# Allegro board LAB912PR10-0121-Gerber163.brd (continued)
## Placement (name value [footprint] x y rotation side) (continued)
PR501  499_0402_1%  [R_0402]  118.02 153.56 270 bottom
PR502  2K_0402_1%  [R_0402]  116.16 147.96 0 top
PR503  137K_0402_1%  [R_0402]  118.92 148.85 180 bottom
PR504  2.05K_0402_1%  [R_0402]  118.9 151.51 180 bottom
PR505  2K_0402_1%  [R_0402]  117.11 150.56 270 bottom
PR506  0_0603_5%  [R0603_0OHM]  118.29 139.4 270 top
PR507  215_0402_1%  [R_0402]  117.13 147.02 270 top
PR508  21K_0402_1%  [R_0402]  118.92 147.96 180 bottom
PR509  11K_0402_1%  [R_0402]  118.01 150.06 0 top
PR510  1.91K_0402_1%  [R_0402]  117.05 146.95 0 bottom
PR511  0_0603_5%  [R0603_0OHM]  118.1 145.84 270 bottom
PR512  4.7_0603_5%  [R_0603]  121.66 134.2 0 top
PR513  3.65K_0603_1%  [R_0603]  114.52 151.52 0 top
PR514  61.9K_0402_1%  [R_0402]  123.29 149.65 90 top
PR515  3.83K_0402_1%  [R_0402]  120.17 153.34 270 bottom
PR516  0_0402_5%  [R0402_0OHM]  121.19 153.37 270 bottom
PR518  0_0603_5%  [R0603_0OHM]  121.82 143.58 270 bottom
PR519  1_0603_5%  [R_0603]  124.79 142.11 90 bottom
PR520  20_0402_1%  [R_0402]  122.37 153.3 270 bottom
PR521  16.9_0402_1%  [R_0402]  123.26 153.3 270 bottom
PR522  1.91K_0402_1%  [R_0402]  123.22 143.34 270 bottom
PR523  3.83K_0402_1%  [R_0402]  125.04 152.37 90 bottom
PR524  0_0402_5%  [R0402_0OHM]  126.82 153.29 270 bottom
PR525  499_0402_1%  [R_0402]  125.04 152.41 180 top
PR526  69.8_0402_1%  [R_0402]  123.26 153.3 270 top
PR527  69.8_0402_1%  [R_0402]  122.37 153.3 270 top
PR528  0_0603_5%  [R0603_0OHM]  134.49 135.72 180 top
PR529  61.9K_0402_1%  [R_0402]  125.93 153.29 270 bottom
PR530  1.91K_0402_1%  [R_0402]  127.7 147.07 0 bottom
PR531  0_0603_5%  [R0603_0OHM]  128.34 146.09 270 bottom
PR532  4.7_0603_5%  [R_0603]  129.41 134.2 180 top
PR533  2K_0402_1%  [R_0402]  129.49 149.72 90 bottom
PR534  64.9K_0402_1%  [R_0402]  128.61 147.96 180 bottom
PR535  2.61K_0402_1%  [R_0402]  128.48 151.01 0 top
PR536  3.65K_0603_1%  [R_0603]  129.63 152.15 180 top
PR538  499_0402_1%  [R_0402]  127.79 152.48 270 bottom
PR539  2K_0402_1%  [R_0402]  128.99 146.06 0 top
PR540  182_0402_1%  [R_0402]  128.99 146.95 0 top
PR541  11K_0402_1%  [R_0402]  128.48 150.12 0 top
PR542  1.78K_0402_1%  [R_0402]  128.81 152.48 270 bottom
PR543  137K_0402_1%  [R_0402]  128.6 150.64 270 bottom
PR700  0.01_1206_1%  [R_1206_4P-D]  118.8 164.04 0 bottom
PR701  200K_0402_1%  [R_0402]  95.59 150.74 270 top
PR702  200K_0402_1%  [R_0402]  136.84 163.71 90 top
PR703  150K_0402_1%  [R_0402]  132.01 170.72 270 top
PR704  10_0402_5%  [R_0402]  137.93 157.02 90 top
PR705  10_0402_5%  [R_0402]  137.04 157.02 90 top
PR706  200K_0402_1%  [R_0402]  158.68 164.73 90 top
PR707  10_1206_1%  [R_1206]  147.5 159.66 270 top
PR708  47K_0402_1%  [R_0402]  159.7 165.64 270 top
PR709  4.7_0603_5%  [R_0603]  147.55 156.55 90 bottom
PR710  100K_0402_1%  [R_0402]  144.89 148.66 90 top
PR711  232K_0402_1%  [R_0402]  137.85 154.6 180 top
PR712  200K_0402_5%  [R_0402]  133.03 170.72 270 top
PR713  0_0603_5%  [R0603_0OHM]  143.49 159.85 270 bottom
PR714  100K_0402_1%  [R_0402]  158.63 169.76 180 top
PR715  49.9K_0402_1%  [R_0402]  140.9 153.49 180 bottom
PR716  158K_0402_1%  [R_0402]  143.87 149.58 270 top
PR717  0_0402_5%  [R0402_0OHM]  142.35 148.66 90 top
PR718  10K_0402_5%  [R_0402]  137.34 170.72 270 top
PR719  0_0402_5%  [R0402_0OHM]  141.46 148.66 90 top
PR720  0.01_1206_1%  [R_1206_4P-D]  164.27 154.43 90 bottom
PR721  4.7_1206_5%  [R_1206]  156.97 152.48 180 top
PR722  100_0402_1%  [R_0402]  140.52 148.66 90 top
PR723  4.7K_0402_5%  [R_0402]  138.23 150.52 180 top
PR724  10_0402_5%  [R_0402]  148.95 151.96 90 top
PR725  221K_0402_1%  [R_0402]  137.32 152.42 0 top
PR726  100_0402_5%  [R_0402]  146.67 151.23 270 top
PR727  287K_0402_1%  [R_0402]  137.32 153.44 0 top
PR728  28.7K_0402_1%  [R_0402]  137.32 151.4 0 top
PR729  63.4K_0402_1%  [R_0402]  136.38 152.47 90 top
PR730  3.3K_1206_5%~D  [R_1206]  137.92 161.37 180 top
PU100  TPS51225CRUKR QFN 20P PWM  [TPS51225CRUKR_QFN20_3X3]  39.1 48.61 180 top
PU200  -  [RT8207MZQW_WQFN20_3X3]  58.93 51.3 180 top
PU300  -  [SY8032ABC_SOT23-6]  161.66 99.08 270 bottom
PU301  -  [SY8032ABC_SOT23-6]  155.05 117.62 270 bottom
PU400  -  [SY8032ABC_SOT23-6]  45.83 21.23 90 top
PU402  -  [APL5930KAI-TRG_SO8]  157.98 86.6 180 bottom
PU500  -  [ISL95833HRTZ-T_TQFN32_4X4]  121.9 150.5 0 bottom
PU700  ISL88731CHRTZ-T TQFN 28P PWM  [BQ24745RHDR_QFN28_5X5]  140.33 155.27 270 top
Q8  -  [2N7002K_SOT23-3]  166.24 67.31 0 top
Q9  -  [2N7002K_SOT23-3]  108.54 163.14 180 top
Q14  -  [DMN66D0LDW-7_SOT363-6]  20.87 68.22 0 top
Q57  -  [MESS138W-G_SOT323-3]  15.65 71.08 270 bottom
Q58  -  [MESS138W-G_SOT323-3]  15.65 68.54 270 bottom
Q70  -  [2N7002K_SOT23-3]  152.1 92.79 270 bottom
Q71  -  [2N7002K_SOT23-3]  158.65 106.89 90 bottom
Q2307  -  [2N7002K_SOT23-3]  130.36 39.07 90 top
Q2308  -  [2N7002K_SOT23-3]  161.09 81.47 180 bottom
Q2407  -  [MMST3904-7-F_SOT323-3]  58.39 65.53 270 bottom
Q2408  -  [MMST3904-7-F_SOT323-3]  138.02 130.79 180 top
Q6101  DDTA144VCA-7-F-GP  [2N7002K_SOT23-3]  29.46 8.3 0 top
Q6102  DDTA144VCA-7-F-GP  [2N7002K_SOT23-3]  29.48 13 0 top
Q6103  -  [2N7002KW_SOT323-3]  33.83 13.61 0 top
Q6104  DDTA144VCA-7-F-GP  [2N7002K_SOT23-3]  29.43 3.56 0 top
Q6105  -  [2N7002KW_SOT323-3]  145.4 146.68 90 bottom
QA1  DMN66D0LDW-7_SOT363-6~D  [DMN66D0LDW-7_SOT363-6]  160.52 23.69 90 bottom
QA5  -  [DMN66D0LDW-7_SOT363-6]  144.64 26.39 270 bottom
QC1  -  [MESS138W-G_SOT323-3]  138.36 110.13 180 top
QC2  -  [MESS138W-G_SOT323-3]  117.36 114.62 0 top
QC3  -  [MESS138W-G_SOT323-3]  129.04 112.08 0 top
QC4  -  [MESS138W-G_SOT323-3]  131.58 112.08 0 top
QE7  -  [MESS138W-G_SOT323-3]  58.03 72.73 90 bottom
QE8  -  [MESS138W-G_SOT323-3]  58.03 75.27 90 bottom
QE9  -  [MESS138W-G_SOT323-3]  58.03 75.27 270 top
QE10  -  [MESS138W-G_SOT323-3]  101.72 145.81 180 bottom
QE11  -  [MESS138W-G_SOT323-3]  104.07 145.81 180 bottom
QE12  -  [MESS138W-G_SOT323-3]  111.77 160.28 180 top
QM30  -  [2N7002K_SOT23-3]  158.93 49.64 0 bottom
QS2  SI3456BDV-T1-E3 1N TSOP6  [SI3456BDV-T1-E3_TSOP6]  169.97 81.68 180 bottom
QS3  -  [2N7002KW_SOT323-3]  167.48 75.52 270 bottom
R1  47K_0402_5%  [R_0402]  16.14 80.09 180 top
R3  4.7K_0402_5%  [R_0402]  90.4 78.57 0 top
R4  4.7K_0402_5%  [R_0402]  82.78 64.09 0 top
R7  4.7K_0402_5%  [R_0402]  82.78 76.28 0 top
R8  4.7K_0402_5%  [R_0402]  119.18 114.43 90 top
R9  4.7K_0402_5%  [R_0402]  91.32 81.11 180 top
R10  100K_0402_5%  [R_0402]  163.7 67.38 90 top
R11  4.7K_0402_5%  [R_0402]  83.79 70.73 180 top
R16  100K_0402_5%  [R_0402]  168.84 69.38 270 top
R22  0_0402_1%  [R0402_0OHM]  96.2 76.84 90 top
R23  0_0402_1%  [R0402_0OHM]  113.52 117.94 0 top
R24  0_0402_1%  [R0402_0OHM]  97.42 75.01 180 top
R25  0_0402_1%  [R0402_0OHM]  93.1 83.52 180 top
R26  0_0402_1%  [R0402_0OHM]  85.2 65.11 0 top
R27  0_0402_1%  [R0402_0OHM]  84.82 81.24 0 top
R28  0_0402_1%  [R0402_0OHM]  88.7 67.22 270 top
R29  0_0402_1%  [R0402_0OHM]  120.63 116.29 0 top
R30  0_0402_5%  [R_0402]  88.12 69.93 0 top
R31  0_0402_1%  [R0402_0OHM]  84.49 77.43 0 top
R32  0_0402_1%  [R0402_0OHM]  91.32 80.2 180 top
R34  0_0402_1%  [R0402_0OHM]  83.79 69.82 180 top
R36  0_0402_1%  [R0402_0OHM]  54.84 76.25 270 top
R44  0_0402_1%  [R0402_0OHM]  153.98 133.18 90 top
R121  100K_0402_5%  [R_0402]  19.74 68.21 90 top
R122  100K_0402_5%  [R_0402]  21.77 71.25 90 top
R376  10K_0402_5%  [R_0402]  20.76 72.17 270 top
R488  10K_0402_5%  [R_0402]  157.66 150.15 270 bottom
R490  10K_0402_5%  [R_0402]  163.84 51.77 180 top
R696  10K_0402_5%  [R_0402]  147.2 136.99 180 bottom
R697  10K_0402_5%  [R_0402]  147.2 133.69 180 bottom
R926  120K_0402_5%  [R_0402]  65.16 24.85 180 top
R927  100K_0402_5%  [R_0402]  64.24 20.4 0 top
R1022  0_0603_5%  [R0603_0OHM]  109.91 99.59 270 top
R1023  0_0603_5%  [R0603_0OHM]  134.3 99.84 270 top
R1024  10K_0402_5%  [R_0402]  96.5 74 0 top
R1027  4.7K_0402_1%  [R_0402]  69.97 35.49 90 top
R1028  4.7K_0402_1%  [R_0402]  70.99 35.49 90 top
R1029  4.7K_0402_1%  [R_0402]  114.48 29.09 90 top
R1030  4.7K_0402_1%  [R_0402]  113.47 29.09 90 top
R1033  10K_0402_5%  [R_0402]  92.18 84.41 0 top
R1045  0_0603_5%  [R_0603]  147.95 55.71 180 bottom
R1046  10K_0402_5%  [R_0402]  150.04 50.17 90 top
R1047  100K_0402_5%  [R_0402]  143.44 53.88 270 bottom
R1048  2.7K_0402_1%  [R_0402]  144.2 42.96 270 bottom
R1049  0_0402_1%  [R0402_0OHM]  153.04 43.01 180 bottom
R1050  0_0603_5%  [R0603_0OHM]  150.49 52.92 180 bottom
R1051  10K_0402_5%  [R_0402]  151.06 53.37 270 top
R1052  470_0603_5%  [R_0603]  159.25 104.22 180 bottom
R1053  0_0603_5%  [R_0603]  159.43 38.79 180 bottom
R1055  82K_0402_5%  [R_0402]  157.54 79.59 0 bottom
R1056  47K_0402_5%  [R_0402]  157.54 77.3 0 bottom
R1061  10K_0402_5%  [R_0402]  149.33 96.48 0 bottom
R1071  619_0402_1%  [R_0402]  21.22 64.73 0 top
R1072  619_0402_1%  [R_0402]  21.22 63.71 0 top
R1073  619_0402_1%  [R_0402]  21.22 66.76 0 top
R1074  619_0402_1%  [R_0402]  21.22 65.74 0 top
R1075  619_0402_1%  [R_0402]  21.22 62.69 0 top
R1076  619_0402_1%  [R_0402]  21.22 61.68 0 top
R1077  619_0402_1%  [R_0402]  21.22 60.66 0 top
R1078  619_0402_1%  [R_0402]  21.22 59.65 0 top
R1088  0_0402_5%  [R_0402]  96 83.45 45 bottom
R1089  0_0402_5%  [R_0402]  96.63 82.82 45 bottom
R2314  22_0603_5%  [R_0603]  132.58 37.42 180 top
R2315  470_0603_5%  [R_0603]  160.01 79.33 0 bottom
R2354  0_0402_5%  [R_0402]  155.42 150.16 270 bottom
R2355  0_0402_5%  [R_0402]  145.93 19.64 180 bottom
R2356  0_0402_5%  [R_0402]  153.85 25.53 90 bottom
R2358  8.2_0402_1%  [R_0402]  18.17 64.73 180 bottom
R2359  8.2_0402_1%  [R_0402]  18.17 63.71 180 bottom
R2360  8.2_0402_1%  [R_0402]  18.17 66.76 180 bottom
R2361  8.2_0402_1%  [R_0402]  18.17 65.74 180 bottom
R2362  8.2_0402_1%  [R_0402]  18.17 62.7 180 bottom
R2363  8.2_0402_1%  [R_0402]  18.17 61.68 180 bottom
R2364  8.2_0402_1%  [R_0402]  18.17 59.65 180 bottom
R2365  8.2_0402_1%  [R_0402]  18.17 60.66 180 bottom
R2366  0_0402_1%  [R0402_0OHM]  22.46 38.31 0 bottom
R2367  0_0402_1%  [R0402_0OHM]  22.46 37.3 0 bottom
R2368  0_0402_1%  [R0402_0OHM]  22.46 40.34 0 bottom
R2369  0_0402_1%  [R0402_0OHM]  22.46 39.33 0 bottom
R2448  10K_0402_5%  [R_0402]  107.45 109.81 180 top
R2449  2.2K_0402_5%  [R_0402]  107.45 111.84 180 top
R2450  0_0402_5%  [R_0402]  106.53 108.8 0 top
R2451  2.2K_0402_5%  [R_0402]  107.45 110.83 180 top
R3405  100K_0402_5%  [R_0402]  108.78 159.29 0 top
R3406  10K_0402_5%  [R_0402]  112.2 164.21 180 top
R5205  33_0402_5%  [R_0402]  113.96 161.2 90 top
R6103  470R2J-2-GP  [R_0402]  21.09 3.59 0 top
R6104  0_0402_1%  [R0402_0OHM]  31.95 14.92 270 top
R6105  0_0402_1%  [R0402_0OHM]  31.91 10.38 90 top
R6106  0R2J-2-GP  [R_0402]  31.91 5.04 90 top
R6107  390R2J-3-GP  [R_0402]  19.34 3.59 0 top
R6108  330R2J-3-GP  [R_0402]  23.78 3.6 180 top
R6110  10KR2J-3-GP  [R_0402]  148.27 149.89 270 bottom
RA1  100K_0402_5%  [R_0402]  143.69 23.66 270 bottom
RA2  100K_0402_5%  [R_0402]  141.53 25.15 90 bottom
RA3  10K_0402_5%  [R_0402]  144.71 22.74 90 bottom
RA4  0_0402_5%  [R_0402]  145.73 23.66 270 bottom
RA8  0_0402_1%  [R0402_0OHM]  152.63 8.97 0 bottom
RA16  100K_0402_5%~D  [R_0402]  161.6 27.08 270 bottom
RA17  100K_0402_5%~D  [R_0402]  162.49 27.08 270 bottom
RA18  10K_0402_5%~D  [R_0402]  160.71 26.17 90 bottom
RA19  10K_0402_5%  [R_0402]  142.47 19.64 0 bottom
RA20  100K_0402_5%~D  [R_0402]  159.62 22.69 0 bottom
RA29  0_0603_5%  [R_0603]  155.89 8.15 270 bottom
RA30  0_0603_5%  [R_0603]  159.31 25.8 90 bottom
RA31  0_0603_5%  [R_0603]  166.05 21.1 270 bottom
RA32  0_0603_5%  [R_0603]  160.2 8.15 270 bottom
RA34  200K_0402_1%  [R_0402]  148.34 23.71 180 bottom
RA53  2.2K_0402_5%  [R_0402]  150.3 22.99 90 bottom
RA54  10K_0402_5%  [R_0402]  155.63 128.05 270 bottom
RA55  10_0402_1%  [R_0402]  157.21 17.48 0 bottom
RA56  10_0402_1%  [R_0402]  157.21 16.59 0 bottom
RA79  1K_0402_1%  [R_0402]  143.39 20.66 180 bottom
RA80  1K_0402_1%  [R_0402]  157.21 18.37 0 top
RA81  10K_0402_5%  [R_0402]  142.47 21.67 0 bottom
RA82  1K_0402_1%  [R_0402]  157.21 19.26 0 top
RA83  10K_0402_5%  [R_0402]  158.12 17.48 180 top
RA84  10K_0402_5%  [R_0402]  158.12 16.59 180 top
RA130  22_0402_5%  [R_0402]  132.83 106.8 45 bottom
RA154  100K_0402_5%  [R_0402]  160.53 21.67 180 bottom
RA155  100K_0402_5%  [R_0402]  148.34 22.82 180 bottom
RA165  4.7K_0402_5%  [R_0402]  157.21 18.37 0 bottom
RA166  4.7K_0402_5%  [R_0402]  157.21 19.26 0 bottom
RA1109  2.2K_0402_5%  [R_0402]  149.28 22.99 90 bottom
RC1  100K_0402_5%  [R_0402]  131.87 85.76 135 top
RC2  100K_0402_5%  [R_0402]  132.5 86.4 135 top
RC3  23.2_0402_1%  [R_0402]  130.6 84.49 135 top
RC4  29.4_0402_1%  [R_0402]  131.23 85.13 135 top
RC5  162_0402_1%  [R_0402]  129.96 83.86 135 top
RC6  4.7K_0402_1%  [R_0402]  136.57 80.99 90 bottom
RC7  4.7K_0402_1%  [R_0402]  135.68 80.99 90 bottom
RC8  2.2K_0402_5%  [R_0402]  119.13 84.69 225 top
RC9  402_0402_1%  [R_0402]  119.59 99.01 225 top
RC10  10K_0402_5%  [R_0402]  110.95 77.41 135 bottom
RC11  10K_0402_5%  [R_0402]  111.07 78.81 315 bottom
RC12  402_0402_1%  [R_0402]  122.93 98.93 45 top
RC13  402_0402_1%  [R_0402]  120.86 99 135 top
RC14  49.9_0402_1%  [R_0402]  131.01 104.51 45 bottom
RC15  73.2_0402_1%  [R_0402]  107.81 82.56 45 bottom
RC16  10K_0402_5%  [R_0402]  129.75 96.24 135 top
RC17  10K_0402_5%  [R_0402]  140.34 109.81 180 top
RC18  10K_0402_5%  [R_0402]  116.52 111.64 0 top
RC19  1M_0402_5%  [R_0402]  111.71 103.71 225 bottom
RC20  4.7K_0402_5%  [R_0402]  90.4 69.55 0 top
RC21  2.2K_0402_5%  [R_0402]  110.62 85.5 225 top
RC22  47.5_0402_1%  [R_0402]  113.74 97.44 315 top
RC23  4.02K_0402_1%  [R_0402]  114.94 96.18 315 top
RC24  0_0402_5%  [R_0402]  124.92 110.68 135 bottom
RC26  100K_0402_5%  [R_0402]  97.41 86.39 225 bottom
RC27  73.2_0402_1%  [R_0402]  105.53 77.6 45 bottom
RC28  20_0402_1%  [R_0402]  107.45 79.51 225 bottom
RC29  16.9_0402_1%  [R_0402]  109.56 81.35 225 bottom
RC30  10K_0402_5%  [R_0402]  83.5 72.52 90 top
RC31  10M_0402_5%  [R_0402]  101.49 90.6 315 bottom
RC32  49.9_0402_1%  [R_0402]  116.14 89.03 0 top
RC33  1K_0402_5%  [R_0402]  54.59 8.47 0 bottom
RC34  20K_0402_1%  [R_0402]  95.36 84.09 45 bottom
RC35  20K_0402_1%  [R_0402]  103.24 87.02 315 bottom
RC36  3.3K_0402_5%  [R_0402]  91.67 68.37 0 bottom
RC37  3.3K_0402_5%  [R_0402]  103.99 70.23 180 bottom
RC38  3.3K_0402_5%  [R_0402]  91.67 70.42 0 bottom
RC39  33_0402_5%  [R_0402]  103.06 71.2 0 bottom
RC40  1.24K_0402_1%  [R_0402]  112.41 94.93 45 top
RC41  1K_0402_1%  [R_0402]  107.55 89.87 0 top
RC42  1K_0402_1%  [R_0402]  110.11 91.59 225 top
RC43  10K_0402_5%  [R_0402]  123.13 111.51 0 top
RC44  10K_0402_5%  [R_0402]  105.64 85.33 45 bottom
RC45  45.3_0402_1%  [R_0402]  109.56 93.04 225 top
RC46  10K_0402_5%  [R_0402]  106.43 84.55 45 bottom
RC47  0_0402_5%  [R_0402]  113.68 94.96 225 top
RC48  10K_0402_5%  [R_0402]  124.04 110.62 180 top
RC49  45.3_0402_1%  [R_0402]  100.25 94.7 315 bottom
RC50  49.9_0402_1%  [R_0402]  124.44 103.46 0 top
RC51  22_0402_5%  [R_0402]  131.15 109.29 225 bottom
RC52  22_0402_5%  [R_0402]  130.38 109.93 225 bottom
RC53  4.7K_0402_5%  [R_0402]  114.36 113.92 0 top
RC54  0_0402_1%  [R0402_0OHM]  130.34 89.16 180 top
RC55  100_0402_1%  [R_0402]  118.88 110.7 270 top
RC56  100_0402_1%  [R_0402]  119.39 88.35 270 top
RC57  49.9_0402_1%  [R_0402]  118.32 99.83 180 top
RC58  100_0402_1%  [R_0402]  117.2 85.14 135 top
RC59  49.9_0402_1%  [R_0402]  133.93 101.54 45 bottom
RC60  10K_0402_5%  [R_0402]  129.93 106.83 225 bottom
RC61  200_0402_5%  [R_0402]  35.24 79.38 90 top
RC62  1K_0402_5%  [R_0402]  36.25 79.38 90 top
RC63  51_0402_5%  [R_0402]  41.33 80.3 270 top
RC65  51_0402_5%  [R_0402]  111.11 86.89 315 top
RC67  0_0402_1%  [R0402_0OHM]  114.92 110 45 bottom
RC68  10K_0402_5%  [R_0402]  137.09 98.46 270 bottom
RC69  1M_0402_5%  [R_0402]  151.06 41.03 90 bottom
RC70  150_0402_1%  [R_0402]  15.55 63.76 90 bottom
RC71  150_0402_1%  [R_0402]  15.55 65.79 90 bottom
RC72  150_0402_1%  [R_0402]  15.55 61.73 90 bottom
RC73  150_0402_1%  [R_0402]  15.55 60.61 270 bottom
RC99  0_0402_1%  [R0402_0OHM]  92.58 69.38 180 bottom
RC100  0_0402_1%  [R0402_0OHM]  120.62 87.85 45 top
RC102  0_0402_1%  [R0402_0OHM]  132.98 100.41 180 top
RD3  470_0402_5%  [R_0402]  80.19 29.85 90 top
RD4  0_0402_1%  [R0402_0OHM]  111.44 29.09 90 top
RD5  0_0402_1%  [R0402_0OHM]  79.18 29.85 90 top
RD6  10K_0402_5%  [R_0402]  128.12 35.77 0 top
RD7  10K_0402_5%  [R_0402]  128.12 36.66 0 top
RD8  0_0402_1%  [R0402_0OHM]  108.4 34.15 0 top
RD9  0_0402_1%  [R0402_0OHM]  109.4 31.88 90 top
RD15  0_0402_1%  [R0402_0OHM]  149.15 149.89 270 bottom
RE1  10K_0402_5%  [R_0402]  144 142.32 0 bottom
RE2  0_0603_5%  [R0603_0OHM]  58.16 67.39 0 top
RE3  100K_0402_1%  [R_0402]  164.27 126.4 270 bottom
RE5  20K_0402_1%  [R_0402]  165.23 127.34 180 bottom
RE6  0_0805_5%  [R0805_0OHM]  159.19 125.39 270 bottom
RE7  0_0402_5%  [R_0402]  158.68 127.13 90 bottom
RE9  4.7K_0402_5%  [R_0402]  54.97 79.01 0 top
RE10  4.7K_0402_5%  [R_0402]  55.12 77.57 0 top
RE11  100K_0402_1%  [R_0402]  157.66 128.05 270 bottom
RE12  0_0402_1%  [R0402_0OHM]  147.2 142.32 180 bottom
RE13  0_0402_1%  [R0402_0OHM]  150.76 132.67 180 top
RE14  0_0402_5%  [R_0402]  147.2 132.67 180 bottom
RE15  0_0402_5%  [R_0402]  158.43 134.15 270 top
RE16  0_0402_5%  [R_0402]  157.41 134.15 270 top
RE17  2.2K_0402_5%  [R_0402]  59.37 72.27 90 bottom
RE18  100K_0402_1%  [R_0402]  164.27 149.23 90 bottom
RE19  2.2K_0402_5%  [R_0402]  59.37 75.47 270 bottom
RE20  10K_0402_5%  [R_0402]  60.38 74.56 90 top
RE21  0_0603_5%  [R0603_0OHM]  150.3 146.07 270 top
RE22  0_0402_1%  [R0402_0OHM]  158.43 130.18 90 top
RE23  0_0402_1%  [R0402_0OHM]  157.41 130.18 90 top
RE25  0_0603_5%  [R0603_0OHM]  151.93 149.19 0 bottom
RE26  0_0603_5%  [R_0603]  58.16 68.66 0 top
RE28  10K_0402_5%  [R_0402]  59.42 76.54 0 top
RE29  0_0402_5%  [R_0402]  59.37 74.56 90 top
RE30  2.2K_0402_5%  [R_0402]  54.08 76.03 0 bottom
RE31  2.2K_0402_5%  [R_0402]  54.08 73.49 0 bottom
RE32  0_0402_5%  [R_0402]  60.38 72.27 90 bottom
RE33  0_0402_5%  [R_0402]  60.38 75.47 270 bottom
RE34  2.2K_0402_5%  [R_0402]  53.92 74.42 0 top
RE36  43_0402_1%  [R_0402]  146.28 135.97 0 bottom
RE43  43_0402_1%  [R_0402]  147.2 140.8 180 bottom
RE49  100K_0402_5%  [R_0402]  169.31 170.47 90 top
RE50  10K_0402_5%  [R_0402]  98.1 148.72 270 bottom
RE60  240_0402_1%  [R_0402]  167.6 114.24 180 top
RI5  0_0402_1%  [R0402_0OHM]  161.21 52.55 90 bottom
RI6  0_0402_1%  [R0402_0OHM]  160.19 52.55 90 bottom
RM7  0_1206_5%  [R_1206]  161.41 41.36 0 bottom
RM8  0_0402_5%  [R_0402]  169.64 52.75 180 top
RM9  0_0402_1%  [R0402_0OHM]  168.73 50.85 0 top
RM11  100K_0402_5%  [R_0402]  169.68 54.69 180 top
RM110  10K_0402_5%  [R_0402]  167.19 49.82 270 top
RP1  100K_0804_8P4R_5%  [RP_0804_8P4R]  91.69 64.61 180 top
RP15  2.2K_0804_8P4R_5%  [RP_0804_8P4R]  15.91 68.72 90 top
RP36  2.2K_0804_8P4R_5%  [RP_0804_8P4R]  157.93 135.65 90 top
RP54  8.2K_8P4R_5%  [RP_0804_8P4R]  133.75 110.43 90 top
RP63  10K_0804_8P4R_5%  [RP_0804_8P4R]  120.42 110.68 90 top
RP64  33_0804_8P4R_5%  [RP_0804_8P4R]  132.93 104.86 225 bottom
RP65  10K_0804_8P4R_5%  [RP_0804_8P4R]  114.68 85.04 270 top
RP66  51_0804_8P4R_5%  [RP_0804_8P4R]  76.27 67.2 90 top
RP67  22_0804_8P4R_5%  [RP_0804_8P4R]  97.2 73.17 90 bottom
RP68  2.2K_0804_8P4R_5%  [RP_0804_8P4R]  127.9 109.81 45 bottom
RR1  6.19K_0402_1%  [R_0402]  12.83 18.12 180 bottom
RR2  22_0402_5%  [R_0402]  22.33 21.42 0 bottom
RR4  0_0402_1%  [R0402_0OHM]  12.83 20.15 180 bottom
RR5  0_0402_1%  [R0402_0OHM]  12.83 19.13 180 bottom
RR9  0_0603_5%  [R0603_0OHM]  11.23 22.5 90 bottom
RS6  100K_0402_5%  [R_0402]  167.52 78.44 180 bottom
RS7  0_0402_1%  [R0402_0OHM]  169.2 23.02 90 bottom
RS8  0_0402_1%  [R0402_0OHM]  170.08 23.93 270 bottom
RS09  0_0402_5%  [R_0402]  152.74 79.94 0 top
RS9  470K_0402_5%  [R_0402]  166.6 77.43 0 bottom
RS10  0_0402_5%  [R_0402]  152.77 84.36 0 top
RS12  0_0805_5%  [R0805_0OHM]  165.92 86.28 270 bottom
RT17  100K_0402_5%  [R_0402]  99.75 160.84 180 bottom
RT18  100K_0402_5%  [R_0402]  97.97 160.84 180 bottom
RV54  0_0805_5%  [R0805_0OHM]  146.61 9.77 90 bottom
RV59  0_0603_5%  [R0603_0OHM]  154.62 6.75 90 bottom
RV299  0_0805_5%  [R0805_0OHM]  96.56 150.58 0 bottom
RX1  0_0402_5%  [R_0402]  110.42 161.06 90 bottom
RX2  2.2K_0402_5%  [R_0402]  102.24 142.71 180 bottom
RX3  2.2K_0402_5%  [R_0402]  104.53 142.58 180 bottom
RX4  0_0402_5%  [R_0402]  169.04 142.07 180 bottom
RX5  0_0402_1%  [R0402_0OHM]  150.04 149.89 270 bottom
RX7  0_0402_1%  [R0402_0OHM]  100.49 152.85 270 bottom
RX9  10K_0402_5%  [R_0402]  105 158.86 90 bottom
RX10  10K_0402_5%  [R_0402]  101.39 153.12 0 bottom
RX12  10K_0402_5%  [R_0402]  16.29 72.85 180 top
RX19  0_0402_1%  [R0402_0OHM]  108.78 158.4 0 top
RX20  0_0402_5%  [R_0402]  106.01 159.77 270 bottom
RX21  0_0402_1%  [R0402_0OHM]  106.99 159.74 270 bottom
RX22  0_0402_1%  [R0402_0OHM]  108.01 159.74 270 bottom
RX23  0_0402_5%  [R_0402]  108.78 157.51 0 top
RX24  100K_0402_5%  [R_0402]  111.3 161.06 90 bottom
RX25  0_0402_5%  [R_0402]  104.08 158 0 bottom
RX26  100K_0402_5%  [R_0402]  103.98 158.86 90 bottom
RX27  0_0603_5%  [R0603_0OHM]  109.11 161.36 270 bottom
RX28  0_0603_1%  [R0603_0OHM]  107.28 155.63 270 bottom
RX30  0_0603_5%  [R0603_0OHM]  110.27 154.26 90 bottom
RX39  10K_0402_5%  [R_0402]  103.56 147.86 270 bottom
RX40  10K_0402_5%  [R_0402]  102.55 147.86 270 bottom
RX41  10K_0402_5%  [R_0402]  112.2 163.32 180 top
RX42  10K_0402_5%  [R_0402]  111.56 159.2 0 top
SW1  SMT1-05-A_4P  [SW_SMT1-05-A_4P]  15.51 13.87 270 bottom
SW2  SMT1-05-A_4P  [SW_SMT1-05-A_4P]  33.64 11.17 0 top
T8  PAD  [TPC12]  112.96 89.11 0 top
T15  -  [TPC12]  170.3 49.88 0 top
T97  PAD  [TPC12]  112.73 79.92 180 bottom
T98  PAD  [TPC12]  113.59 80.86 180 bottom
T99  PAD  [TPC12]  104.7 146.92 90 bottom
T100  PAD  [TPC12]  130.6 103.13 180 bottom
T101  PAD  [TPC12]  129.01 104.68 180 bottom
T102  PAD  [TPC12]  126.33 103.4 0 top
T103  PAD  [TPC12]  127.44 98.13 0 top
T104  PAD  [TPC12]  114.73 88.18 90 top
T105  PAD  [TPC12]  109.59 84.41 270 bottom
T106  PAD  [TPC12]  122.82 103.03 0 top
T107  PAD  [TPC12]  124.95 102.48 0 top
T109  PAD  [TPC12]  101.43 146.85 90 bottom
T110  PAD  [TPC12]  135.9 100.08 270 bottom
T111  PAD  [TPC12]  134.11 98.92 270 bottom
T112  PAD  [TPC12]  117.93 91.17 90 top
T113  PAD  [TPC12]  132.53 101.35 180 bottom
T114  PAD  [TPC12]  131.64 102.34 180 bottom
T195  PAD  [TPC12]  122.85 91.78 90 top
T197  PAD  [TPC12]  162.72 129.24 0 bottom
T203  PAD  [TPC12]  146.23 139.78 0 bottom
T209  PAD  [TPC12]  160.79 143.71 90 top
T210  PAD  [TPC12]  148.28 135.03 0 bottom
T211  PAD  [TPC12]  131.36 110.48 180 bottom
T212  PAD  [TPC12]  156.47 131.87 180 top
T217  PAD  [TPC12]  108.46 108.8 0 top
T218  PAD  [TPC12]  145.22 135.97 270 bottom
T221  PAD  [TPC12]  148.27 136.74 270 bottom
U11  -  [AOZ1331DI_DFN14-10]  61.54 20.93 90 top
U12  -  [AOZ1331DI_DFN14-10]  156.1 80.08 270 bottom
U58  FE1.1S-BSOP28BCTR_SSOP28  [FE1P1S-BSOP28BCTR_SSOP28]  152.39 45.2 180 bottom
U60  ME4856_SO8  [AO4304L_SO8]  155.25 100.37 180 bottom
U68  NL17SZ07DFT2G_SC70-5  [SN74LVC1G07DCKR_SC70-5]  86.65 69.28 90 top
U69  NL17SZ07DFT2G_SC70-5  [SN74LVC1G07DCKR_SC70-5]  94.78 79.95 90 top
U70  -  [TCS20DLR_SOT23F-3]  11.58 79.08 90 top
U2407  -  [F75303M_MSOP10]  100.01 112.08 270 top
UA1  -  [ALC3234-CG_MQFN48_6X6]  148.6 15.41 90 bottom
UC5  NL17SZ07DFT2G_SC70-5  [SN74LVC1G07DCKR_SC70-5]  94.78 68.78 90 top
UC7  NL17SZ07DFT2G_SC70-5  [SN74LVC1G07DCKR_SC70-5]  86.65 72.08 90 top
UC8  -  [W25Q64DWSSIG_SO8]  94.15 67.44 90 bottom
UC10  NL17SZ07DFT2G_SC70-5  [SN74LVC1G07DCKR_SC70-5]  114.17 110.77 0 top
UE1  -  [KB9022QC_LQFP128_14X14]  151.76 146.4 270 bottom
UE3  -  [NCT3942S_SO8]  92.26 140.84 0 bottom
UE4  TPS22967DSGR_SON8_2X2  [AOZ1336_DFN8_2X2]  57.76 71.45 270 top
UI4  -  [SY6288D20AAC_SOT23-5]  159.63 40.54 180 bottom
UI5  -  [SY6288D20AAC_SOT23-5]  23.88 42.82 90 bottom
UR1  RTS5170-GR_QFN24_4X4  [RTS5179-GR_QFN24_4X4]  15.93 19.9 90 bottom
USOC1  FH8065301546401_FCBGA131170  [FH8065301546401_FCBGA13_1170P]  104.6 92.76 135 bottom
UX1  -  [APL3512ABI-TRG_SOT23-5]  98.23 154.13 270 bottom
UX3  -  [APL3512ABI-TRG_SOT23-5]  113.24 158.87 270 bottom
UX4  -  [SY6288C20AAC_SOT23-5]  100.91 156.67 0 bottom
Y9  12MHZ_12PF_5YEA12000122IFA2Q3  [Y_5YEA12000122IFA2Q3_4P]  147.92 39.12 90 bottom
YC1  25MHZ_10PF_7V25000014  [Y_7V25000014_4P]  110.1 105.97 225 bottom
YC2  32.768KHZ_12.5PF_CM7V-12520  [Y_CM7V-12520_2P]  97.34 89.11 315 bottom

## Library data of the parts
C1-C3 C967 C976 C979 C980 C1034-C1055 C1058 C1060-C1076 C1078 C1117 C1118 C1121-C1128 C1131-C1133 C1138 C1139 C1143-C1148 C2498 C2500 C2502 C2504 C2505 CA21 CA22 CA24 CA25 CA29-CA32 CA51 CA54 CA56 CA58 CA60 CA65 CA69 CC1 CC2 CC5-CC32 CC39-CC47 CC49-CC54 CC56 CC57 CC59 CC61 CC63 CC65 CD1-CD11 CD21 CD22 CD24-CD27 CD30 CD31 CD33-CD47 CE1 CE2 CE5-CE10 CE12 CE18 CE20 CE23 CE26-CE29 CE31 CE32 CE34-CE36 CE59-CE61 CI2-CI4 CI7 CI13-CI15 CI17 CI26 CM5 CM7-CM9 CR1 CR3 CR4 CR6 CR7 CR9 CR11 CS5 CS6 CS8-CS11 CS13-CS15 CS17 CS30-CS32 CS34 CX6 CX9 CX11-CX19 CX21 CX42-CX47 CX50 CX52 EC6104 PC1-PC12 PC106 PC107 PC109 PC110 PC203 PC204 PC211 PC212 PC214-PC216 PC301 PC304-PC306 PC309 PC310 PC401 PC404 PC405 PC411 PC413 PC415 PC502-PC508 PC511 PC512 PC514 PC516 PC520 PC521 PC523 PC525-PC529 PC531-PC535 PC701 PC704 PC708 PC712 PC715 PC716 PC721 PC723 PC725 PC727 PC923-PC928 PC933 PC934 = C_0402
C1056 C1057 C1059 C2307 CC36 CC38 CE16 CI6 CI12 CI18 CS7 CS12 CX7 CX8 CX49 CX51 PC108 PC111 PC118 PC205 PC206 PC208 PC209 PC509 PC510 PC519 PC522 PC702 PC703 PC717-PC720 = C_0805
C1119 C1120 C1129 C1130 C2305 C2306 C2308 C2316 C2318 C2323 C2324 CA1 CA2 CA23 CA53 CA55 CA57 CA59 CA61-CA64 CA67 CA68 CA71 CA74 CC33-CC35 CD12-CD14 CD16-CD20 CD28 CD29 CD62 CE24 CE25 CI40 CM4 CM6 CR2 CR8 CS16 CX5 CX10 CX22 PC105 PC112-PC117 PC207 PC210 PC213 PC300 PC302 PC303 PC307 PC308 PC311 PC400 PC402 PC403 PC412 PC414 PC513 PC515 PC517 PC518 PC524 PC530 PC700 PC705-PC707 PC709-PC711 PC713 PC714 PC722 PC726 PC901-PC908 PC913-PC916 PC920-PC922 PC929-PC932 = C_0603
CD15 CD32 PC102 PC103 PC201 PC501 PC536 PC909 PC911 PC917-PC919 = C_D2
CI1 = C_1206
CI19 = C_B15G
CLIP1 = EMIST-SQ-26G_1P
CLIP2 CLIP3 = EMIST_SQ-55G_1P
CLRP1 = SHORTPADS: User Part Number: PART#
D25-D27 = YSLC05CH_SOT23-3
D2401 DX1 DX2 = RB751V-40_SOD323-2
DA8 = BAT54C-7-F_SOT23-3
DC1 = DB2J31400L_SOD323-2
DC3 = LBAV70WT1G_SC70-3
DE3 = PESD5V0U2BT_SOT23-3
DI1 = IP4292CZ10-TBR_XSON10_2P5X1
FD1-FD4 = FIDUCIAL_C40M80
FX1 = F_1206L150PR
FX2 = F_MINISMDC150F-24
H1 = H_3P2
H2 = H_4P0N
H3 H4 H9 H10 = H_3P0
H5 H6 H11 H12 = H_3P3
H7 = H_3P0X3P8N
JDB1 = MOLEX_52435-2671_26P-T
JDIMM2 = FOX_AS0A621-J4RB-7H_204P-T
JEDP = ACES_51540-04001-P01_40P-T
JFAN = ACES_50224-0030N-001_3P-T
JHDD = ACES_51625-01201-001_12P-T
JHDMI1 = C-K_96067-3K28-192-124_19P-T
JIO1 = ACES_51524-0240N-001_24P
JKB = ACES_51510-0304N-P01_30P
JNGFF = DAN05-67406-0100_67P-T
JODD1 = ACES_51519-02001-001_20P-T
JP7 JP13 JP38 JP39 PJP4 PJP303 PJP500 = JUMP_43X79
JP12 PJP202 PJP300-PJP302 PJP400 PJP401 PJP404 PJP405 = JUMP_43X39
JP14 JP15 JP36 JP37 PJP1 PJP100-PJP102 PJP200 PJP201 PJP700 = JUMP_43X118
JPWR = JXT_FP202DH-004M10M_4P
JREAD = TAI_PSDATG-11GLBS1NN4H0_11P-T
JRTC = LOTES_AAA-BAT-054-K01_2P
JSPK = ACES_50224-0040N-001_4P-T
JTP = JXT_FP202DH-008M10M_8P
JUSB1 = TAITW_PUBAUN-09FLBS1NN4H0_9P-T
LA1 = MURAT_BLM15BB221SN1D_2P
LA3-LA6 PR107 PR108 PR200 PR506 PR511 PR518 PR528 PR531 PR713 R1022 R1023 R1050 RE2 RE21 RE25 RR9 RV59 RX27 RX28 RX30 = R0603_0OHM
LA7 LA10 = MURAT_BLM15BD601SN1D_2P
LA8 LA9 PR203 PR209 PR301 PR306 PR401 PR512 PR513 PR519 PR532 PR536 PR709 R1045 R1052 R1053 R2314 R2315 RA29-RA32 RE26 = R_0603
LE1 LE2 = KC_FBMA-L11-160808-800LMT_2P
LED1 = LED_12-22A-S2ST3D-C30-2C_3P
LED2 = LED_12-21C-T3D-CM2P1B18X-2C_3P
LI2 LI5 LI6 = INPAQ_HCM2012GA900AE_4P
LX1 = KC_FBMA-L11-201209-221LMA30_2P
PBATT1 = SUYIN_200277GR008M270ZR_8P-T
PD1 PD2 = TVNST52302AB0_SOT523-3
PH1 PH500-PH503 PR1-PR11 PR14 PR16-PR23 PR26 PR34-PR36 PR100-PR106 PR115-PR117 PR201 PR204-PR206 PR210 PR300 PR302-PR305 PR307-PR309 PR400 PR402-PR404 PR409-PR412 PR500-PR505 PR507-PR510 PR514 PR515 PR520-PR523 PR525-PR527 PR529 PR530 PR533-PR535 PR538-PR543 PR701-PR706 PR708 PR710-PR712 PR714-PR716 PR718 PR722-PR729 R1 R3 R4 R7-R11 R16 R30 R121 R122 R376 R488 R490 R696 R697 R926 R927 R1024 R1027-R1030 R1033 R1046-R1048 R1051 R1055 R1056 R1061 R1071-R1078 R1088 R1089 R2354-R2356 R2358-R2365 R2448-R2451 R3405 R3406 R5205 R6103 R6106-R6108 R6110 RA1-RA4 RA16-RA20 RA34 RA53-RA56 RA79-RA84 RA130 RA154 RA155 RA165 RA166 RA1109 RC1-RC24 RC26-RC53 RC55-RC63 RC65 RC68-RC73 RD3 RD6 RD7 RE1 RE3 RE5 RE7 RE9-RE11 RE14-RE20 RE28-RE34 RE36 RE43 RE49 RE50 RE60 RM8 RM11 RM110 RR1 RR2 RS6 RS09 RS9 RS10 RT17 RT18 RX1-RX4 RX9 RX10 RX12 RX20 RX23-RX26 RX39-RX42 = R_0402
PJPDC1 = ACES_50458-00601-001_6P-T
PL1 = MURAT_BLM41PG600SN1L_2P
PL2 PL4 PL102 = MURAT_BLM41PG600SN1L_2P-NPM
PL3 = MURAT_BLM15AG102SN1D_2P
PL100 PL101 PL200 PL700 = L_7X7X3_M_2P
PL300 PL301 PL400 = TOKO_1239AS-H-1R0M-P2_2P
PL500 PL501 = PANAS_ETQP4LR15AFM_4P
PL502 = TAI-T_HCB2012KF-121T50_2P
PL701 = L_4X4X2_F_2P-NPM
PQ1 = FDV301N_NL_SOT23-3
PQ2 = RHU002N06_SOT323-3
PQ3 PQ4 PQ10 PQ709 PQ710 PQ713 = 2N7002DW-T-R7_SOT363-6
PQ101 PQ102 PQ201 = MDV1528URH_PDFN33-8-5
PQ103 PQ104 PQ203 = MDV1527URH_POWERDFN33-8-5
PQ501 PQ503 = AON7934_DFN3X3A8-10
PQ701 PQ703 = SIS412DN-T1-GE3_POWERPAK8-5
PQ704 PQ706 = AO4407AL_SO8
PQ705 = SI4459ADY-T1-GE3_SO8
PQ707 = DTA144EUA_SC70-3
PQ708 PQ711 PQ712 = DTC115EUA_SC70-3
PR12 PR109-PR111 PR202 PR707 PR721 PR730 RM7 = R_1206
PR13 PR15 PR112-PR114 PR207 PR208 PR516 PR524 PR717 PR719 R22-R29 R31 R32 R34 R36 R44 R1049 R2366-R2369 R6104 R6105 RA8 RC54 RC67 RC99 RC100 RC102 RD4 RD5 RD8 RD9 RD15 RE12 RE13 RE22 RE23 RI5 RI6 RM9 RR4 RR5 RS7 RS8 RX5 RX7 RX19 RX21 RX22 = R0402_0OHM
PR700 PR720 = R_1206_4P-D
PU100 = TPS51225CRUKR_QFN20_3X3
PU200 = RT8207MZQW_WQFN20_3X3
PU300 PU301 PU400 = SY8032ABC_SOT23-6
PU402 = APL5930KAI-TRG_SO8
PU500 = ISL95833HRTZ-T_TQFN32_4X4
PU700 = BQ24745RHDR_QFN28_5X5
Q8 Q9 Q70 Q71 Q2307 Q2308 Q6101 Q6102 Q6104 QM30 = 2N7002K_SOT23-3
Q14 QA1 QA5 = DMN66D0LDW-7_SOT363-6
Q57 Q58 QC1-QC4 QE7-QE12 = MESS138W-G_SOT323-3
Q2407 Q2408 = MMST3904-7-F_SOT323-3
Q6103 Q6105 QS3 = 2N7002KW_SOT323-3
QS2 = SI3456BDV-T1-E3_TSOP6
RE6 RS12 RV54 RV299 = R0805_0OHM
RP1 RP15 RP36 RP54 RP63-RP68 = RP_0804_8P4R
SW1 SW2 = SW_SMT1-05-A_4P
T8 T15 T97-T107 T109-T114 T195 T197 T203 T209-T212 T217 T218 T221 = TPC12
U11 U12 = AOZ1331DI_DFN14-10
U58 = FE1P1S-BSOP28BCTR_SSOP28
U60 = AO4304L_SO8
U68 U69 UC5 UC7 UC10 = SN74LVC1G07DCKR_SC70-5
U70 = TCS20DLR_SOT23F-3
U2407 = F75303M_MSOP10
UA1 = ALC3234-CG_MQFN48_6X6
UC8 = W25Q64DWSSIG_SO8
UE1 = KB9022QC_LQFP128_14X14
UE3 = NCT3942S_SO8
UE4 = AOZ1336_DFN8_2X2
UI4 UI5 = SY6288D20AAC_SOT23-5
UR1 = RTS5179-GR_QFN24_4X4
USOC1 = FH8065301546401_FCBGA13_1170P
UX1 UX3 = APL3512ABI-TRG_SOT23-5
UX4 = SY6288C20AAC_SOT23-5
Y9 = Y_5YEA12000122IFA2Q3_4P
YC1 = Y_7V25000014_4P
YC2 = Y_CM7V-12520_2P

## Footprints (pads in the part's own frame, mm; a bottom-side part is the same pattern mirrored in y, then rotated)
2N7002DW-T-R7_SOT363-6
  oval 0.381x1.397 smd: 1(0,0) 2(0.65,0) 3(1.3,0) 4(1.3,1.725) 5(0.65,1.725) 6(0,1.725)
2N7002K_SOT23-3
  oval 1.016x1.524 smd: 1(0,0) 2(0.965,2.083) 3(-0.965,2.083)
2N7002KW_SOT323-3
  oval 0.813x0.914 smd: 1(0,0) 2(0.65,1.6) 3(-0.65,1.6)
ACES_50224-0030N-001_3P-T
  oval 0.61x1.549 smd: 1(0,0) 2(1,0) 3(2,0)
  rect 1.194x1.803 smd: 4(3.3,-3.875) 5(-1.3,-3.875)
ACES_50224-0040N-001_4P-T
  oval 0.61x1.549 smd: 1(0,0) 2(1,0) 3(2,0) 4(3,0)
  rect 1.194x1.803 smd: 5(-1.3,-3.875) 6(4.3,-3.875)
ACES_50458-00601-001_6P-T
  oval 0.559x1.6 smd: 1(0,0) 2(2,0) 3(4,0) 4(6,0) 5(8,0) 6(10,0)
  rect 1.295x2.057 smd: 7(-3.1,-5.175) 8(13.1,-5.175)
ACES_51510-0304N-P01_30P
  oval 0.305x1.295 smd: 1(0,0) 2(0.8,0) 3(1.6,0) 4(2.4,0) 5(3.2,0) 6(4,0) 7(4.8,0) 8(5.6,0) 9(6.4,0) 10(7.2,0) 11(8,0) 12(8.8,0) 13(9.6,0) 14(10.4,0) 15(11.2,0) 16(12,0) 17(12.8,0) 18(13.6,0) 19(14.4,0) 20(15.2,0) 21(16,0) 22(16.8,0) 23(17.6,0) 24(18.4,0) 25(19.2,0) 26(20,0) 27(20.8,0) 28(21.6,0) 29(22.4,0) 30(23.2,0)
  rect 1.803x2.21 smd: 31(25.55,-5.65) 32(-2.35,-5.65)
ACES_51519-02001-001_20P-T
  oval 0.305x1.295 smd: 1(0,0) 2(0.5,0) 3(1,0) 4(1.5,0) 5(2,0) 6(2.5,0) 7(3,0) 8(3.5,0) 9(4,0) 10(4.5,0) 11(5,0) 12(5.5,0) 13(6,0) 14(6.5,0) 15(7,0) 16(7.5,0) 17(8,0) 18(8.5,0) 19(9,0) 20(9.5,0)
  rect 1.803x2.21 smd: 21(11.65,-5.65) 22(-2.15,-5.65)
ACES_51524-0240N-001_24P
  oval 0.61x1.295 smd: 1(0,0) 2(1,0) 3(2,0) 4(3,0) 5(4,0) 6(5,0) 7(6,0) 8(7,0) 9(8,0) 10(9,0) 11(10,0) 12(11,0) 13(12,0) 14(13,0) 15(14,0) 16(15,0) 17(16,0) 18(17,0) 19(18,0) 20(19,0) 21(20,0) 22(21,0) 23(22,0) 24(23,0)
  rect 2.489x2.21 smd: 25(-3,-3.05) 26(26,-3.05)
ACES_51540-04001-P01_40P-T
  oval 0.305x1.092 smd: 1(0,0) 2(0.5,0) 3(1,0) 4(1.5,0) 5(2,0) 6(2.5,0) 7(3,0) 8(3.5,0) 9(4,0) 10(4.5,0) 11(5,0) 12(5.5,0) 13(6,0) 14(6.5,0) 15(7,0) 16(7.5,0) 17(8,0) 18(8.5,0) 19(9,0) 20(9.5,0) 21(10,0) 22(10.5,0) 23(11,0) 24(11.5,0) 25(12,0) 26(12.5,0) 27(13,0) 28(13.5,0) 29(14,0) 30(14.5,0) 31(15,0) 32(15.5,0) 33(16,0) 34(16.5,0) 35(17,0) 36(17.5,0) 37(18,0) 38(18.5,0) 39(19,0) 40(19.5,0)
  rect 0.787x2.489 smd: 41(21.2,-3.6) 42(-1.7,-3.6)
ACES_51625-01201-001_12P-T
  oval 0.305x1.092 smd: 1(0,0) 2(0.5,0) 3(1,0) 4(1.5,0) 5(2,0) 6(2.5,0) 7(3,0) 8(3.5,0) 9(4,0) 10(4.5,0) 11(5,0) 12(5.5,0)
  rect 0.991x2.489 smd: 13(7.3,-3.6) 14(-1.8,-3.6)
ALC3234-CG_MQFN48_6X6
  oval 0.203x0.889 smd: 1(0,0) 2(0.4,0) 3(0.8,0) 4(1.2,0) 5(1.6,0) 6(2,0) 7(2.4,0) 8(2.8,0) 9(3.2,0) 10(3.6,0) 11(4,0) 12(4.4,0) 25(4.4,6.1) 26(4,6.1) 27(3.6,6.1) 28(3.2,6.1) 29(2.8,6.1) 30(2.4,6.1) 31(2,6.1) 32(1.6,6.1) 33(1.2,6.1) 34(0.8,6.1) 35(0.4,6.1) 36(0,6.1)
  oval 0.889x0.203 smd: 13(5.25,0.85) 14(5.25,1.25) 15(5.25,1.65) 16(5.25,2.05) 17(5.25,2.45) 18(5.25,2.85) 19(5.25,3.25) 20(5.25,3.65) 21(5.25,4.05) 22(5.25,4.45) 23(5.25,4.85) 24(5.25,5.25) 37(-0.85,5.25) 38(-0.85,4.85) 39(-0.85,4.45) 40(-0.85,4.05) 41(-0.85,3.65) 42(-0.85,3.25) 43(-0.85,2.85) 44(-0.85,2.45) 45(-0.85,2.05) 46(-0.85,1.65) 47(-0.85,1.25) 48(-0.85,0.85)
  rect 4.394x4.394 smd: 49(2.2,3.05)
AO4304L_SO8
  oval 0.635x1.854 smd: 1(0,0) 2(1.27,0) 3(2.54,0) 4(3.81,0) 5(3.81,5.165) 6(2.54,5.165) 7(1.27,5.165) 8(0,5.165)
AO4407AL_SO8
  oval 0.635x1.854 smd: 1(0,0) 2(1.27,0) 3(2.54,0) 4(3.81,0) 5(3.81,5.165) 6(2.54,5.165) 7(1.27,5.165) 8(0,5.165)
AON7934_DFN3X3A8-10
  oval 0.457x0.508 smd: 1(0,0) 2(0.65,0) 3(1.3,0) 4(1.95,0) 5(1.95,2.76) 6(1.3,2.76) 7(0.65,2.76) 8(0,2.76)
  rect 2.54x1.041 smd: 9(0.975,1.813)
  rect 2.54x0.559 smd: 10(0.975,0.708)
AOZ1331DI_DFN14-10
  custom 0.125x0.125 smd: 1(0,0) 5(2,0) 6(2,1.8) 10(0,1.8)
  oval 0.203x0.508 smd: 2(0.6,0) 3(1,0) 4(1.4,0) 7(1.4,1.8) 8(1,1.8) 9(0.6,1.8)
  rect 2.591x0.889 smd: 11(1,0.9)
AOZ1336_DFN8_2X2
  oval 0.254x0.787 smd: 1(0,0) 2(0.5,0) 3(1,0) 4(1.5,0) 5(1.5,2.2) 6(1,2.2) 7(0.5,2.2) 8(0,2.2)
  rect 1.499x0.889 smd: 9(0.75,1.1)
APL3512ABI-TRG_SOT23-5
  oval 0.61x1.041 smd: 1(0,0) 2(0.95,0) 3(1.9,0) 4(1.9,2.7) 5(0,2.7)
APL5930KAI-TRG_SO8
  oval 0.635x1.854 smd: 1(0,0) 2(1.27,0) 3(2.54,0) 4(3.81,0) 5(3.81,5.165) 6(2.54,5.165) 7(1.27,5.165) 8(0,5.165)
  rect 2.87x2.489 smd: 9(1.905,2.582)
BAT54C-7-F_SOT23-3
  oval 1.016x1.524 smd: 1(0,0) 2(0.965,2.083) 3(-0.965,2.083)
BQ24745RHDR_QFN28_5X5
  oval 0.254x1.194 smd: 1(0,0) 2(0.5,0) 3(1,0) 4(1.5,0) 5(2.001,0) 6(2.501,0) 7(3.001,0) 15(3.001,4.8) 16(2.501,4.8) 17(2.001,4.8) 18(1.5,4.8) 19(1,4.8) 20(0.5,4.8) 21(0,4.8)
  oval 1.194x0.254 smd: 8(3.9,0.9) 9(3.9,1.4) 10(3.9,1.9) 11(3.9,2.4) 12(3.9,2.9) 13(3.9,3.4) 14(3.9,3.9) 22(-0.9,3.9) 23(-0.9,3.4) 24(-0.9,2.9) 25(-0.9,2.4) 26(-0.9,1.9) 27(-0.9,1.4) 28(-0.9,0.9)
  rect 2.692x2.692 smd: 29(1.5,2.4)
C-K_96067-3K28-192-124_19P-T
  round 1.397 hole 1.397 unplated: (-4.4,0.7) (13.4,0.7)
  round 0.813 hole 0.559: 1(0,0) 2(0.5,1.55) 3(1,0) 4(1.5,1.55) 5(2,0) 6(2.5,1.55) 7(3,0) 8(3.5,1.55) 9(4,0) 10(4.5,1.55) 11(5,0) 12(5.5,1.55) 13(6,0) 14(6.5,1.55) 15(7,0) 16(7.5,1.55) 17(8,0) 18(8.5,1.55) 19(9,0)
  oval 1.194x2.692 hole 0.889x2.388: 20(15.3,-7.7) 23(-6.3,-7.7)
  oval 1.194x2.007 hole 0.889x1.702: 21(15.25,0.3) 22(-6.25,0.3)
C_0402
  rect 0.508x0.559 smd: 1(0,0) 2(0.914,0)
C_0603
  rect 0.635x0.889 smd: 1(0,0) 2(1.397,0)
C_0805
  rect 0.813x1.397 smd: 1(0,0) 2(1.702,0)
C_1206
  rect 1.016x1.651 smd: 1(0,0) 2(2.667,0)
C_B15G
  rect 1.6x2.692 smd: 1(0,0) 2(3,0)
C_D2
  rect 2.388x2.794 smd: 1(0,0) 2(6.4,0)
DAN05-67406-0100_67P-T
  round 1.092 hole 1.092 unplated: (-0.75,-5.275)
  round 1.6 hole 1.6 unplated: (19.25,-5.275)
  oval 0.305x1.549 smd: 1(0,0) 2(0.25,-7.55) 3(0.5,0) 4(0.75,-7.55) 5(1,0) 6(1.25,-7.55) 7(1.5,0) 8(3.75,-7.55) 9(4,0) 10(4.25,-7.55) 11(4.5,0) 12(4.75,-7.55) 13(5,0) 14(5.25,-7.55) 15(5.5,0) 16(5.75,-7.55) 17(6,0) 18(6.25,-7.55) 19(6.5,0) 20(6.75,-7.55) 21(7,0) 22(7.25,-7.55) 23(7.5,0) 24(7.75,-7.55) 25(8,0) 26(8.25,-7.55) 27(8.5,0) 28(8.75,-7.55) 29(9,0) 30(9.25,-7.55) 31(9.5,0) 32(9.75,-7.55) 33(10,0) 34(10.25,-7.55) 35(10.5,0) 36(10.75,-7.55) 37(11,0) 38(11.25,-7.55) 39(11.5,0) 40(11.75,-7.55) 41(12,0) 42(12.25,-7.55) 43(12.5,0) 44(12.75,-7.55) 45(13,0) 46(13.25,-7.55) 47(13.5,0) 48(13.75,-7.55) 49(14,0) 50(14.25,-7.55) 51(14.5,0) 52(14.75,-7.55) 53(15,0) 54(15.25,-7.55) 55(15.5,0) 56(15.75,-7.55) 57(16,0) 58(16.25,-7.55) 59(16.5,0) 60(16.75,-7.55) 61(17,0) 62(17.25,-7.55) 63(17.5,0) 64(17.75,-7.55) 65(18,0) 66(18.25,-7.55) 67(18.5,0)
  rect 1.194x2.743 smd: 68(-1.1,-0.775) 69(19.6,-0.775)
DB2J31400L_SOD323-2
  rect 0.991x1.092 smd: 1(0,0)
  rect 0.991x0.889 smd: 2(2.1,0)
DMN66D0LDW-7_SOT363-6
  oval 0.432x0.61 smd: 1(0,0) 2(0.65,0) 3(1.3,0) 4(1.3,1.9) 5(0.65,1.9) 6(0,1.9)
DTA144EUA_SC70-3
  rect 0.813x0.914 smd: 1(0,0) 2(0.65,1.6) 3(-0.65,1.6)
DTC115EUA_SC70-3
  oval 0.813x0.914 smd: 1(0,0) 2(0.65,1.6) 3(-0.65,1.6)
EMIST-SQ-26G_1P
  rect 5.105x2.794 smd: 1(0,0)
EMIST_SQ-55G_1P
  rect 7.798x3.658 smd: 1(0,0)
F75303M_MSOP10
  oval 0.254x1.626 smd: 1(0,0) 2(0.5,0) 3(1,0) 4(1.5,0) 5(2,0) 6(2,4.3) 7(1.5,4.3) 8(1,4.3) 9(0.5,4.3) 10(0,4.3)
F_1206L150PR
  rect 0.991x1.803 smd: 1(0,0) 2(2.8,0)
F_MINISMDC150F-24
  rect 3.759x1.118 smd: 1(0,0) 2(0,-4)
FDV301N_NL_SOT23-3
  oval 1.016x1.524 smd: 1(0,0) 2(0.965,2.083) 3(-0.965,2.083)
FE1P1S-BSOP28BCTR_SSOP28
  oval 0.381x1.727 smd: 1(0,0) 2(0.635,0) 3(1.27,0) 4(1.905,0) 5(2.54,0) 6(3.175,0) 7(3.81,0) 8(4.445,0) 9(5.08,0) 10(5.715,0) 11(6.35,0) 12(6.985,0) 13(7.62,0) 14(8.255,0) 15(8.255,5.28) 16(7.62,5.28) 17(6.985,5.28) 18(6.35,5.28) 19(5.715,5.28) 20(5.08,5.28) 21(4.445,5.28) 22(3.81,5.28) 23(3.175,5.28) 24(2.54,5.28) 25(1.905,5.28) 26(1.27,5.28) 27(0.635,5.28) 28(0,5.28)
FH8065301546401_FCBGA13_1170P
  round 0.521 smd: A3(-0.863,0) A52(-25.197,0) B2(-0.431,0.431) B53(-25.628,0.431) BH1(0,23.197) BH53(-25.628,23.197) BJ2(-0.431,23.628) BJ52(-25.197,23.628) C1(0,0.863)
  round 0.406 smd: A5(-1.644,0) A6(-2.368,0) A49(-23.806,0) A51(-24.587,0) B52(-25.039,0.589) BE1(0,21.806) BE53(-25.628,21.806) BG1(0,22.587) BG53(-25.628,22.587) BH2(-0.589,23.039) BH52(-25.039,23.039) BJ3(-1.041,23.628) BJ5(-1.822,23.628) BJ49(-23.806,23.628) BJ51(-24.587,23.628) C53(-25.628,1.041) E1(0,1.644) E53(-25.628,1.822) F1(0,2.368)
  round 0.356 smd: A7(-3.066,0) A9(-3.978,0) A47(-22.435,0) A48(-23.108,0) B4(-1.182,0.576) B5(-1.776,0.592) B6(-2.369,0.593) B8(-3.556,0.59) B46(-22.072,0.59) B48(-23.259,0.593) B49(-23.852,0.592) B50(-24.446,0.576) BC1(0,20.435) BC2(-0.568,20.666) BC52(-25.06,20.666) BC53(-25.628,20.435) BD1(0,21.108) BD2(-0.593,21.259) BD52(-25.035,21.259) BD53(-25.628,21.108) BE2(-0.592,21.852) BE52(-25.037,21.852) BF2(-0.576,22.446) BF52(-25.052,22.446) BG3(-1.17,22.458) BG51(-24.458,22.458) BH4(-1.182,23.052) BH5(-1.776,23.037) BH6(-2.369,23.035) BH8(-3.556,23.038) BH46(-22.072,23.038) BH48(-23.259,23.035) BH49(-23.852,23.037) BH50(-24.446,23.052) BJ6(-2.52,23.628) BJ7(-3.194,23.628) BJ47(-22.435,23.628) BJ48(-23.108,23.628) C3(-1.17,1.17) C51(-24.458,1.17) D2(-0.576,1.182) D52(-25.052,1.182) E2(-0.592,1.776) E52(-25.037,1.776) F2(-0.593,2.369) F52(-25.035,2.369) F53(-25.628,2.52) G1(0,3.135) G2(-0.568,2.962) G52(-25.06,2.962) G53(-25.628,3.194) J1(0,3.998)
  oval 0.254x0.343 smd: A11(-5.04,0) A13(-6.011,0) A15(-6.983,0) A17(-7.955,0) A19(-8.927,0) A21(-9.899,0) A23(-10.87,0) A25(-11.842,0) A27(-12.814,0) A29(-13.786,0) A31(-14.758,0) A33(-15.729,0) A35(-16.701,0) A37(-17.673,0) A39(-18.645,0) A41(-19.617,0) A43(-20.588,0) A45(-21.56,0) BJ9(-4.068,23.628) BJ11(-5.04,23.628) BJ13(-6.011,23.628) BJ15(-6.983,23.628) BJ17(-7.955,23.628) BJ19(-8.927,23.628) BJ21(-9.899,23.628) BJ23(-10.87,23.628) BJ25(-11.842,23.628) BJ27(-12.814,23.628) BJ29(-13.786,23.628) BJ31(-14.758,23.628) BJ33(-15.729,23.628) BJ35(-16.701,23.628) BJ37(-17.673,23.628) BJ39(-18.645,23.628) BJ41(-19.617,23.628) BJ43(-20.588,23.628) BJ45(-21.56,23.628)
  oval 0.343x0.254 smd: AA1(0,9.87) AA53(-25.628,9.87) AC1(0,10.842) AC53(-25.628,10.842) AE1(0,11.814) AE53(-25.628,11.814) AG1(0,12.786) AG53(-25.628,12.786) AJ1(0,13.758) AJ53(-25.628,13.758) AL1(0,14.729) AL53(-25.628,14.729) AN1(0,15.701) AN53(-25.628,15.701) AR1(0,16.673) AR53(-25.628,16.673) AU1(0,17.645) AU53(-25.628,17.645) AW1(0,18.617) AW53(-25.628,18.617) BA1(0,19.588) BA53(-25.628,19.588) J53(-25.628,4.04) L1(0,5.011) L53(-25.628,5.011) N1(0,5.983) N53(-25.628,5.983) R1(0,6.955) R53(-25.628,6.955) U1(0,7.927) U53(-25.628,7.927) W1(0,8.899) W53(-25.628,8.899)
  round 0.279 smd: AA3(-0.743,9.87) AA51(-24.885,9.87) AB2(-0.385,10.356) AB3(-1.084,10.356) AB51(-24.544,10.356) AB52(-25.243,10.356) AC3(-0.743,10.842) AC51(-24.885,10.842) AD2(-0.385,11.328) AD3(-1.099,11.334) AD51(-24.529,11.334) AD52(-25.243,11.328) AE3(-0.743,11.814) AE4(-1.448,11.814) AE50(-24.18,11.814) AE51(-24.885,11.814) AF2(-0.385,12.3) AF3(-1.099,12.294) AF51(-24.529,12.294) AF52(-25.243,12.3) AG3(-0.743,12.786) AG51(-24.885,12.786) AH2(-0.385,13.272) AH3(-1.084,13.272) AH51(-24.544,13.272) AH52(-25.243,13.272) AJ3(-0.743,13.758) AJ51(-24.885,13.758) AK2(-0.385,14.244) AK3(-1.084,14.244) AK51(-24.544,14.244) AK52(-25.243,14.244) AL3(-0.743,14.729) AL51(-24.885,14.729) AM2(-0.385,15.215) AM3(-1.084,15.215) AM51(-24.544,15.215) AM52(-25.243,15.215) AN3(-0.743,15.701) AN51(-24.885,15.701) AP2(-0.385,16.187) AP3(-1.084,16.187) AP51(-24.544,16.187) AP52(-25.243,16.187) AR3(-0.743,16.673) AR51(-24.885,16.673) AT2(-0.385,17.159) AT3(-1.084,17.159) AT51(-24.544,17.159) AT52(-25.243,17.159) AU3(-0.743,17.645) AU51(-24.885,17.645) AV2(-0.385,18.131) AV3(-1.084,18.131) AV51(-24.544,18.131) AV52(-25.243,18.131) AW3(-0.743,18.617) AW51(-24.885,18.617) AY2(-0.385,19.103) AY3(-1.084,19.103) AY51(-24.544,19.103) AY52(-25.243,19.103) B10(-4.554,0.385) B12(-5.526,0.385) B14(-6.497,0.385) B16(-7.469,0.385) B18(-8.441,0.385) B20(-9.413,0.385) B22(-10.385,0.385) B24(-11.356,0.385) B26(-12.328,0.385) B28(-13.3,0.385) B30(-14.272,0.385) B32(-15.244,0.385) B34(-16.215,0.385) B36(-17.187,0.385) B38(-18.159,0.385) B40(-19.131,0.385) B42(-20.103,0.385) B44(-21.074,0.385) BA3(-0.743,19.588) BA51(-24.885,19.588) BB3(-0.885,20.165) BB51(-24.743,20.165) BF27(-12.814,22.18) BG9(-4.116,22.842) BG11(-5.04,22.885) BG12(-5.526,22.544) BG13(-6.011,22.885) BG14(-6.497,22.544) BG15(-6.983,22.885) BG16(-7.469,22.544) BG17(-7.955,22.885) BG18(-8.441,22.544) BG19(-8.927,22.885) BG20(-9.413,22.544) BG21(-9.899,22.885) BG22(-10.385,22.544) BG23(-10.87,22.885) BG24(-11.356,22.544) BG25(-11.842,22.885) BG26(-12.334,22.529) BG27(-12.814,22.885) BG28(-13.294,22.529) BG29(-13.786,22.885) BG30(-14.272,22.544) BG31(-14.758,22.885) BG32(-15.244,22.544) BG33(-15.729,22.885) BG34(-16.215,22.544) BG35(-16.701,22.885) BG36(-17.187,22.544) BG37(-17.673,22.885) BG38(-18.159,22.544) BG39(-18.645,22.885) BG40(-19.131,22.544) BG41(-19.617,22.885) BG42(-20.103,22.544) BG43(-20.588,22.885) BG45(-21.512,22.842) BH10(-4.554,23.243) BH12(-5.526,23.243) BH14(-6.497,23.243) BH16(-7.469,23.243) BH18(-8.441,23.243) BH20(-9.413,23.243) BH22(-10.385,23.243) BH24(-11.356,23.243) BH26(-12.328,23.243) BH28(-13.3,23.243) BH30(-14.272,23.243) BH32(-15.244,23.243) BH34(-16.215,23.243) BH36(-17.187,23.243) BH38(-18.159,23.243) BH40(-19.131,23.243) BH42(-20.103,23.243) BH44(-21.074,23.243) C9(-4.116,0.786) C11(-5.04,0.743) C12(-5.526,1.084) C13(-6.011,0.743) C14(-6.497,1.084) C15(-6.983,0.743) C16(-7.469,1.084) C17(-7.955,0.743) C18(-8.441,1.084) C19(-8.927,0.743) C20(-9.413,1.084) C21(-9.899,0.743) C22(-10.385,1.084) C23(-10.87,0.743) C24(-11.356,1.084) C25(-11.842,0.743) C26(-12.334,1.099) C27(-12.814,0.743) C28(-13.294,1.099) C29(-13.786,0.743) C30(-14.272,1.084) C31(-14.758,0.743) C32(-15.244,1.084) C33(-15.729,0.743) C34(-16.215,1.084) C35(-16.701,0.743) C36(-17.187,1.084) C37(-17.673,0.743) C38(-18.159,1.084) C39(-18.645,0.743) C40(-19.131,1.084) C41(-19.617,0.743) C42(-20.103,1.084) C43(-20.588,0.743) C45(-21.512,0.786) D27(-12.814,1.448) H3(-0.885,3.463) H51(-24.743,3.463) J3(-0.743,4.04) J51(-24.885,4.04) K2(-0.385,4.526) K3(-1.084,4.526) K51(-24.544,4.526) K52(-25.243,4.526) L3(-0.743,5.011) L51(-24.885,5.011) M2(-0.385,5.497) M3(-1.084,5.497) M51(-24.544,5.497) M52(-25.243,5.497) N3(-0.743,5.983) N51(-24.885,5.983) P2(-0.385,6.469) P3(-1.084,6.469) P51(-24.544,6.469) P52(-25.243,6.469) R3(-0.743,6.955) R51(-24.885,6.955) T2(-0.385,7.441) T3(-1.084,7.441) T51(-24.544,7.441) T52(-25.243,7.441) U3(-0.743,7.927) U51(-24.885,7.927) V2(-0.385,8.413) V3(-1.084,8.413) V51(-24.544,8.413) V52(-25.243,8.413) W3(-0.743,8.899) W51(-24.885,8.899) Y2(-0.385,9.385) Y3(-1.084,9.385) Y51(-24.544,9.385) Y52(-25.243,9.385)
  round 0.33 smd: AA16(-7.507,9.853) AA18(-8.265,9.853) AA19(-9.023,9.853) AA21(-9.781,9.853) AA22(-10.539,9.853) AA24(-11.298,9.853) AA25(-12.056,9.853) AA27(-12.814,9.853) AA29(-13.572,9.853) AA30(-14.33,9.853) AA32(-15.089,9.853) AA33(-15.847,9.853) AA35(-16.605,9.853) AA36(-17.363,9.853) AA38(-18.121,9.853) AC16(-7.507,10.638) AC18(-8.265,10.638) AC19(-9.023,10.638) AC21(-9.781,10.638) AC22(-10.539,10.638) AC24(-11.298,10.638) AC25(-12.056,10.638) AC27(-12.814,10.638) AC29(-13.572,10.638) AC30(-14.33,10.638) AC32(-15.089,10.638) AC33(-15.847,10.638) AC35(-16.605,10.638) AC36(-17.363,10.638) AC38(-18.121,10.638) AD16(-7.507,11.422) AD18(-8.265,11.422) AD19(-9.023,11.422) AD21(-9.781,11.422) AD22(-10.539,11.422) AD24(-11.298,11.422) AD25(-12.056,11.422) AD27(-12.814,11.422) AD29(-13.572,11.422) AD30(-14.33,11.422) AD32(-15.089,11.422) AD33(-15.847,11.422) AD35(-16.605,11.422) AD36(-17.363,11.422) AD38(-18.121,11.422) AF16(-7.507,12.206) AF18(-8.265,12.206) AF19(-9.023,12.206) AF21(-9.781,12.206) AF22(-10.539,12.206) AF24(-11.298,12.206) AF25(-12.056,12.206) AF27(-12.814,12.206) AF29(-13.572,12.206) AF30(-14.33,12.206) AF32(-15.089,12.206) AF33(-15.847,12.206) AF35(-16.605,12.206) AF36(-17.363,12.206) AF38(-18.121,12.206) AG16(-7.507,12.991) AG18(-8.265,12.991) AG19(-9.023,12.991) AG21(-9.781,12.991) AG22(-10.539,12.991) AG24(-11.298,12.991) AG25(-12.056,12.991) AG27(-12.814,12.991) AG29(-13.572,12.991) AG30(-14.33,12.991) AG32(-15.089,12.991) AG33(-15.847,12.991) AG35(-16.605,12.991) AG36(-17.363,12.991) AG38(-18.121,12.991) AJ16(-7.507,13.775) AJ18(-8.265,13.775) AJ19(-9.023,13.775) AJ21(-9.781,13.775) AJ22(-10.539,13.775) AJ24(-11.298,13.775) AJ25(-12.056,13.775) AJ27(-12.814,13.775) AJ29(-13.572,13.775) AJ30(-14.33,13.775) AJ32(-15.089,13.775) AJ33(-15.847,13.775) AJ35(-16.605,13.775) AJ36(-17.363,13.775) AJ38(-18.121,13.775) AK16(-7.507,14.559) AK18(-8.265,14.559) AK19(-9.023,14.559) AK21(-9.781,14.559) AK22(-10.539,14.559) AK24(-11.298,14.559) AK25(-12.056,14.559) AK27(-12.814,14.559) AK29(-13.572,14.559) AK30(-14.33,14.559) AK32(-15.089,14.559) AK33(-15.847,14.559) AK35(-16.605,14.559) AK36(-17.363,14.559) AK38(-18.121,14.559) AM16(-7.507,15.344) AM18(-8.265,15.344) AM19(-9.023,15.344) AM21(-9.781,15.344) AM22(-10.539,15.344) AM24(-11.298,15.344) AM25(-12.056,15.344) AM27(-12.814,15.344) AM29(-13.572,15.344) AM30(-14.33,15.344) AM32(-15.089,15.344) AM33(-15.847,15.344) AM35(-16.605,15.344) AM36(-17.363,15.344) AM38(-18.121,15.344) AN16(-7.507,16.128) AN18(-8.265,16.128) AN19(-9.023,16.128) AN21(-9.781,16.128) AN22(-10.539,16.128) AN24(-11.298,16.128) AN25(-12.056,16.128) AN27(-12.814,16.128) AN29(-13.572,16.128) AN30(-14.33,16.128) AN32(-15.089,16.128) AN33(-15.847,16.128) AN35(-16.605,16.128) AN36(-17.363,16.128) AN38(-18.121,16.128) U16(-7.507,7.5) U18(-8.265,7.5) U19(-9.023,7.5) U21(-9.781,7.5) U22(-10.539,7.5) U24(-11.298,7.5) U25(-12.056,7.5) U27(-12.814,7.5) U29(-13.572,7.5) U30(-14.33,7.5) U32(-15.089,7.5) U33(-15.847,7.5) U35(-16.605,7.5) U36(-17.363,7.5) U38(-18.121,7.5) V16(-7.507,8.284) V18(-8.265,8.284) V19(-9.023,8.284) V21(-9.781,8.284) V22(-10.539,8.284) V24(-11.298,8.284) V25(-12.056,8.284) V27(-12.814,8.284) V29(-13.572,8.284) V30(-14.33,8.284) V32(-15.089,8.284) V33(-15.847,8.284) V35(-16.605,8.284) V36(-17.363,8.284) V38(-18.121,8.284) Y16(-7.507,9.069) Y18(-8.265,9.069) Y19(-9.023,9.069) Y21(-9.781,9.069) Y22(-10.539,9.069) Y24(-11.298,9.069) Y25(-12.056,9.069) Y27(-12.814,9.069) Y29(-13.572,9.069) Y30(-14.33,9.069) Y32(-15.089,9.069) Y33(-15.847,9.069) Y35(-16.605,9.069) Y36(-17.363,9.069) Y38(-18.121,9.069)
  round 0.305 smd: AB4(-1.677,10.366) AB6(-2.351,10.366) AB7(-3.062,10.366) AB9(-3.773,10.366) AB10(-4.484,10.366) AB12(-5.196,10.366) AB13(-5.907,10.366) AB14(-6.618,10.366) AB40(-19.01,10.366) AB41(-19.721,10.366) AB42(-20.433,10.366) AB44(-21.144,10.366) AB45(-21.855,10.366) AB47(-22.566,10.366) AB48(-23.277,10.366) AB50(-23.951,10.366) AD4(-1.819,11.351) AD6(-2.41,11.289) AD7(-3.062,11.339) AD9(-3.773,11.339) AD10(-4.484,11.339) AD12(-5.196,11.339) AD13(-5.907,11.339) AD14(-6.618,11.339) AD40(-19.01,11.339) AD41(-19.721,11.339) AD42(-20.433,11.339) AD44(-21.144,11.339) AD45(-21.855,11.339) AD47(-22.566,11.339) AD48(-23.218,11.289) AD50(-23.809,11.351) AE6(-2.706,11.814) AE8(-3.418,11.814) AE9(-4.129,11.814) AE11(-4.84,11.814) AE12(-5.551,11.814) AE14(-6.262,11.814) AE40(-19.366,11.814) AE42(-20.077,11.814) AE43(-20.788,11.814) AE45(-21.499,11.814) AE46(-22.211,11.814) AE48(-22.922,11.814) AF4(-1.819,12.277) AF6(-2.41,12.339) AF7(-3.062,12.289) AF9(-3.773,12.289) AF10(-4.484,12.289) AF12(-5.196,12.289) AF13(-5.907,12.289) AF14(-6.618,12.289) AF40(-19.01,12.289) AF41(-19.721,12.289) AF42(-20.433,12.289) AF44(-21.144,12.289) AF45(-21.855,12.289) AF47(-22.566,12.289) AF48(-23.218,12.339) AF50(-23.809,12.277) AH4(-1.677,13.262) AH6(-2.351,13.262) AH7(-3.062,13.262) AH9(-3.773,13.262) AH10(-4.484,13.262) AH12(-5.196,13.262) AH13(-5.907,13.262) AH14(-6.618,13.262) AH40(-19.01,13.262) AH41(-19.721,13.262) AH42(-20.433,13.262) AH44(-21.144,13.262) AH45(-21.855,13.262) AH47(-22.566,13.262) AH48(-23.277,13.262) AH50(-23.951,13.262) AK4(-1.677,14.253) AK6(-2.351,14.253) AK7(-3.062,14.253) AK9(-3.773,14.253) AK10(-4.484,14.253) AK12(-5.196,14.253) AK13(-5.907,14.253) AK14(-6.618,14.253) AK40(-19.01,14.253) AK41(-19.721,14.253) AK42(-20.433,14.253) AK44(-21.144,14.253) AK45(-21.855,14.253) AK47(-22.566,14.253) AK48(-23.277,14.253) AK50(-23.951,14.253) AM4(-1.677,15.2) AM6(-2.351,15.226) AM7(-3.062,15.226) AM9(-3.773,15.226) AM10(-4.484,15.226) AM12(-5.196,15.226) AM13(-5.907,15.226) AM14(-6.618,15.226) AM40(-19.01,15.226) AM41(-19.721,15.226) AM42(-20.433,15.226) AM44(-21.144,15.226) AM45(-21.855,15.226) AM47(-22.566,15.226) AM48(-23.277,15.226) AM50(-23.951,15.2) AN5(-1.995,15.701) AN6(-2.706,15.701) AN8(-3.418,15.701) AN9(-4.129,15.701) AN11(-4.84,15.701) AN12(-5.551,15.701) AN14(-6.262,15.701) AN40(-19.366,15.701) AN42(-20.077,15.701) AN43(-20.788,15.701) AN45(-21.499,15.701) AN46(-22.211,15.701) AN48(-22.922,15.701) AN49(-23.633,15.701) AP4(-1.677,16.202) AP6(-2.351,16.176) AP7(-3.062,16.176) AP9(-3.773,16.176) AP10(-4.484,16.176) AP12(-5.196,16.176) AP13(-5.907,16.176) AP14(-6.618,16.176) AP40(-19.01,16.176) AP41(-19.721,16.176) AP42(-20.433,16.176) AP44(-21.144,16.176) AP45(-21.855,16.176) AP47(-22.566,16.176) AP48(-23.277,16.176) AP50(-23.951,16.202) AT4(-1.677,17.15) AT6(-2.351,17.15) AT7(-3.062,17.15) AT9(-3.773,17.15) AT10(-4.484,17.15) AT12(-5.196,17.15) AT13(-5.907,17.15) AT14(-6.509,17.15) AT16(-7.479,17.01) AT18(-8.452,17.01) AT19(-8.927,17.366) AT20(-9.402,17.01) AT22(-10.375,17.01) AT24(-11.366,17.01) AT26(-12.339,17.01) AT27(-12.814,17.366) AT28(-13.289,17.01) AT30(-14.262,17.01) AT32(-15.253,17.01) AT34(-16.226,17.01) AT35(-16.701,17.366) AT36(-17.176,17.01) AT38(-18.15,17.01) AT40(-19.119,17.15) AT41(-19.721,17.15) AT42(-20.433,17.15) AT44(-21.144,17.15) AT45(-21.855,17.15) AT47(-22.566,17.15) AT48(-23.277,17.15) AT50(-23.951,17.15) AU16(-7.479,17.721) AU18(-8.452,17.721) AU20(-9.402,17.721) AU22(-10.375,17.721) AU24(-11.366,17.721) AU26(-12.339,17.721) AU28(-13.289,17.721) AU30(-14.262,17.721) AU32(-15.253,17.721) AU34(-16.226,17.721) AU36(-17.176,17.721) AU38(-18.15,17.721) AV4(-1.677,18.14) AV6(-2.351,18.14) AV7(-3.062,18.14) AV9(-3.773,18.14) AV10(-4.484,18.14) AV12(-5.196,18.14) AV13(-5.907,18.14) AV14(-6.488,18.26) AV16(-7.479,18.433) AV18(-8.452,18.433) AV19(-8.927,18.077) AV20(-9.402,18.433) AV22(-10.375,18.433) AV24(-11.366,18.433) AV26(-12.339,18.433) AV27(-12.814,18.077) AV28(-13.289,18.433) AV30(-14.262,18.433) AV32(-15.253,18.433) AV34(-16.226,18.433) AV35(-16.701,18.077) AV36(-17.176,18.433) AV38(-18.15,18.433) AV40(-19.14,18.26) AV41(-19.721,18.14) AV42(-20.433,18.14) AV44(-21.144,18.14) AV45(-21.855,18.14) AV47(-22.566,18.14) AV48(-23.277,18.14) AV50(-23.951,18.14) AW13(-6.063,18.729) AW19(-8.927,18.788) AW27(-12.814,18.788) AW35(-16.701,18.788) AW41(-19.565,18.729) AY4(-1.677,19.131) AY6(-2.351,19.131) AY7(-3.062,19.131) AY9(-3.773,19.131) AY10(-4.484,19.131) AY12(-5.497,19.154) AY14(-6.488,19.144) AY16(-7.479,19.144) AY18(-8.452,19.144) AY20(-9.402,19.144) AY22(-10.375,19.144) AY24(-11.366,19.144) AY26(-12.339,19.144) AY28(-13.289,19.144) AY30(-14.262,19.144) AY32(-15.253,19.144) AY34(-16.226,19.144) AY36(-17.176,19.144) AY38(-18.15,19.144) AY40(-19.14,19.144) AY42(-20.131,19.154) AY44(-21.144,19.131) AY45(-21.855,19.131) AY47(-22.566,19.131) AY48(-23.277,19.131) AY50(-23.951,19.131) B7(-2.962,0.584) B47(-22.666,0.584) BA12(-5.497,19.855) BA14(-6.488,19.855) BA16(-7.479,19.855) BA18(-8.452,19.855) BA19(-8.927,19.499) BA20(-9.402,19.855) BA22(-10.375,19.855) BA24(-11.366,19.855) BA26(-12.339,19.855) BA27(-12.814,19.499) BA28(-13.289,19.855) BA30(-14.262,19.855) BA32(-15.253,19.855) BA34(-16.226,19.855) BA35(-16.701,19.499) BA36(-17.176,19.855) BA38(-18.15,19.855) BA40(-19.14,19.855) BA42(-20.131,19.855) BB4(-1.556,20.121) BB5(-2.267,20.121) BB7(-2.979,20.121) BB8(-3.69,20.121) BB10(-4.507,19.984) BB19(-8.927,20.211) BB27(-12.814,20.211) BB35(-16.701,20.211) BB44(-21.121,19.984) BB46(-21.938,20.121) BB47(-22.649,20.121) BB49(-23.361,20.121) BB50(-24.072,20.121) BC10(-4.507,20.578) BC12(-5.497,20.566) BC14(-6.488,20.566) BC16(-7.479,20.566) BC18(-8.452,20.566) BC20(-9.402,20.566) BC22(-10.375,20.566) BC24(-11.366,20.566) BC26(-12.339,20.566) BC28(-13.289,20.566) BC30(-14.262,20.566) BC32(-15.253,20.566) BC34(-16.226,20.566) BC36(-17.176,20.566) BC38(-18.15,20.566) BC40(-19.14,20.566) BC42(-20.131,20.566) BC44(-21.121,20.578) BD5(-2.249,21.116) BD7(-3.102,21.116) BD10(-4.507,21.271) BD12(-5.497,21.277) BD14(-6.488,21.277) BD16(-7.479,21.277) BD18(-8.452,21.277) BD19(-8.927,20.922) BD20(-9.402,21.277) BD22(-10.375,21.277) BD24(-11.366,21.277) BD26(-12.289,21.218) BD27(-12.814,20.922) BD28(-13.339,21.218) BD30(-14.262,21.277) BD32(-15.253,21.277) BD34(-16.226,21.277) BD35(-16.701,20.922) BD36(-17.176,21.277) BD38(-18.15,21.277) BD40(-19.14,21.277) BD42(-20.131,21.277) BD44(-21.121,21.271) BD47(-22.526,21.116) BD49(-23.379,21.116) BE3(-1.171,21.394) BE8(-3.494,21.561) BE19(-8.927,21.633) BE35(-16.701,21.633) BE46(-22.134,21.561) BE51(-24.457,21.394) BF4(-1.651,21.977) BF6(-2.701,22.053) BF10(-4.507,21.982) BF12(-5.497,21.951) BF14(-6.488,21.951) BF16(-7.479,21.951) BF18(-8.426,21.951) BF20(-9.428,21.951) BF22(-10.375,21.951) BF24(-11.366,21.951) BF26(-12.351,21.809) BF28(-13.277,21.809) BF30(-14.262,21.951) BF32(-15.253,21.951) BF34(-16.2,21.951) BF36(-17.202,21.951) BF38(-18.15,21.951) BF40(-19.14,21.951) BF42(-20.131,21.951) BF44(-21.121,21.982) BF48(-22.927,22.053) BF50(-23.977,21.977) BG5(-2.234,22.457) BG7(-3.261,22.523) BG47(-22.367,22.523) BG49(-23.394,22.457) BH7(-2.962,23.044) BH47(-22.666,23.044) C5(-2.234,1.171) C7(-3.261,1.105) C47(-22.367,1.105) C49(-23.394,1.171) D4(-1.651,1.651) D6(-2.701,1.576) D10(-4.507,1.646) D12(-5.497,1.677) D14(-6.488,1.677) D16(-7.479,1.677) D18(-8.426,1.677) D20(-9.428,1.677) D22(-10.375,1.677) D24(-11.366,1.677) D26(-12.351,1.819) D28(-13.277,1.819) D30(-14.262,1.677) D32(-15.253,1.677) D34(-16.2,1.677) D36(-17.202,1.677) D38(-18.15,1.677) D40(-19.14,1.677) D42(-20.131,1.677) D44(-21.121,1.646) D48(-22.927,1.576) D50(-23.977,1.651) E3(-1.171,2.234) E8(-3.494,2.067) E19(-8.927,1.995) E35(-16.701,1.995) E46(-22.134,2.067) E51(-24.457,2.234) F5(-2.249,2.512) F7(-3.102,2.512) F10(-4.507,2.357) F12(-5.497,2.351) F14(-6.488,2.351) F16(-7.479,2.351) F18(-8.452,2.351) F19(-8.927,2.706) F20(-9.402,2.351) F22(-10.375,2.351) F24(-11.366,2.351) F26(-12.289,2.41) F27(-12.814,2.706) F28(-13.339,2.41) F30(-14.262,2.351) F32(-15.253,2.351) F34(-16.226,2.351) F35(-16.701,2.706) F36(-17.176,2.351) F38(-18.15,2.351) F40(-19.14,2.351) F42(-20.131,2.351) F44(-21.121,2.357) F47(-22.526,2.512) F49(-23.379,2.512) G10(-4.507,3.05) G12(-5.497,3.062) G14(-6.488,3.062) G16(-7.479,3.062) G18(-8.452,3.062) G20(-9.402,3.062) G22(-10.375,3.062) G24(-11.366,3.062) G26(-12.339,3.062) G28(-13.289,3.062) G30(-14.262,3.062) G32(-15.253,3.062) G34(-16.226,3.062) G36(-17.176,3.062) G38(-18.15,3.062) G40(-19.14,3.062) G42(-20.131,3.062) G44(-21.121,3.05) H4(-1.556,3.507) H5(-2.267,3.507) H7(-2.979,3.507) H8(-3.69,3.507) H10(-4.507,3.644) H19(-8.927,3.418) H27(-12.814,3.418) H35(-16.701,3.418) H44(-21.121,3.644) H46(-21.938,3.507) H47(-22.649,3.507) H49(-23.361,3.507) H50(-24.072,3.507) J12(-5.497,3.773) J14(-6.488,3.773) J16(-7.479,3.773) J18(-8.452,3.773) J19(-8.927,4.129) J20(-9.402,3.773) J22(-10.375,3.773) J24(-11.366,3.773) J26(-12.339,3.773) J27(-12.814,4.129) J28(-13.289,3.773) J30(-14.262,3.773) J32(-15.253,3.773) J34(-16.226,3.773) J35(-16.701,4.129) J36(-17.176,3.773) J38(-18.15,3.773) J40(-19.14,3.773) J42(-20.131,3.773) K4(-1.677,4.497) K6(-2.351,4.497) K7(-3.062,4.497) K9(-3.773,4.497) K10(-4.484,4.497) K12(-5.497,4.474) K14(-6.488,4.484) K16(-7.479,4.484) K18(-8.452,4.484) K20(-9.402,4.484) K22(-10.375,4.484) K24(-11.366,4.484) K26(-12.339,4.484) K28(-13.289,4.484) K30(-14.262,4.484) K32(-15.253,4.484) K34(-16.226,4.484) K36(-17.176,4.484) K38(-18.15,4.484) K40(-19.14,4.484) K42(-20.131,4.474) K44(-21.144,4.497) K45(-21.855,4.497) K47(-22.566,4.497) K48(-23.277,4.497) K50(-23.951,4.497) L13(-6.063,4.899) L19(-8.927,4.84) L27(-12.814,4.84) L35(-16.701,4.84) L41(-19.565,4.899) M4(-1.677,5.488) M6(-2.351,5.488) M7(-3.062,5.488) M9(-3.773,5.488) M10(-4.484,5.488) M12(-5.196,5.488) M13(-5.907,5.488) M14(-6.488,5.368) M16(-7.479,5.196) M18(-8.452,5.196) M19(-8.927,5.551) M20(-9.402,5.196) M22(-10.375,5.196) M24(-11.366,5.196) M26(-12.339,5.196) M27(-12.814,5.551) M28(-13.289,5.196) M30(-14.262,5.196) M32(-15.253,5.196) M34(-16.226,5.196) M35(-16.701,5.551) M36(-17.176,5.196) M38(-18.15,5.196) M40(-19.14,5.368) M41(-19.721,5.488) M42(-20.433,5.488) M44(-21.144,5.488) M45(-21.855,5.488) M47(-22.566,5.488) M48(-23.277,5.488) M50(-23.951,5.488) N16(-7.479,5.907) N18(-8.452,5.907) N20(-9.402,5.907) N22(-10.375,5.907) N24(-11.366,5.907) N26(-12.339,5.907) N28(-13.289,5.907) N30(-14.262,5.907) N32(-15.253,5.907) N34(-16.226,5.907) N36(-17.176,5.907) N38(-18.15,5.907) P4(-1.677,6.479) P6(-2.351,6.479) P7(-3.062,6.479) P9(-3.773,6.479) P10(-4.484,6.479) P12(-5.196,6.479) P13(-5.907,6.479) P14(-6.509,6.479) P16(-7.479,6.618) P18(-8.452,6.618) P19(-8.927,6.262) P20(-9.402,6.618) P22(-10.375,6.618) P24(-11.366,6.618) P26(-12.339,6.618) P27(-12.814,6.262) P28(-13.289,6.618) P30(-14.262,6.618) P32(-15.253,6.618) P34(-16.226,6.618) P35(-16.701,6.262) P36(-17.176,6.618) P38(-18.15,6.618) P40(-19.119,6.479) P41(-19.721,6.479) P42(-20.433,6.479) P44(-21.144,6.479) P45(-21.855,6.479) P47(-22.566,6.479) P48(-23.277,6.479) P50(-23.951,6.479) T4(-1.677,7.426) T6(-2.351,7.452) T7(-3.062,7.452) T9(-3.773,7.452) T10(-4.484,7.452) T12(-5.196,7.452) T13(-5.907,7.452) T14(-6.618,7.452) T40(-19.01,7.452) T41(-19.721,7.452) T42(-20.433,7.452) T44(-21.144,7.452) T45(-21.855,7.452) T47(-22.566,7.452) T48(-23.277,7.452) T50(-23.951,7.426) U5(-1.995,7.927) U6(-2.706,7.927) U8(-3.418,7.927) U9(-4.129,7.927) U11(-4.84,7.927) U12(-5.551,7.927) U14(-6.262,7.927) U40(-19.366,7.927) U42(-20.077,7.927) U43(-20.788,7.927) U45(-21.499,7.927) U46(-22.211,7.927) U48(-22.922,7.927) U49(-23.633,7.927) V4(-1.677,8.428) V6(-2.351,8.402) V7(-3.062,8.402) V9(-3.773,8.402) V10(-4.484,8.402) V12(-5.196,8.402) V13(-5.907,8.402) V14(-6.618,8.402) V40(-19.01,8.402) V41(-19.721,8.402) V42(-20.433,8.402) V44(-21.144,8.402) V45(-21.855,8.402) V47(-22.566,8.402) V48(-23.277,8.402) V50(-23.951,8.428) Y4(-1.677,9.375) Y6(-2.351,9.375) Y7(-3.062,9.375) Y9(-3.773,9.375) Y10(-4.484,9.375) Y12(-5.196,9.375) Y13(-5.907,9.375) Y14(-6.618,9.375) Y40(-19.01,9.375) Y41(-19.721,9.375) Y42(-20.433,9.375) Y44(-21.144,9.375) Y45(-21.855,9.375) Y47(-22.566,9.375) Y48(-23.277,9.375) Y50(-23.951,9.375)
